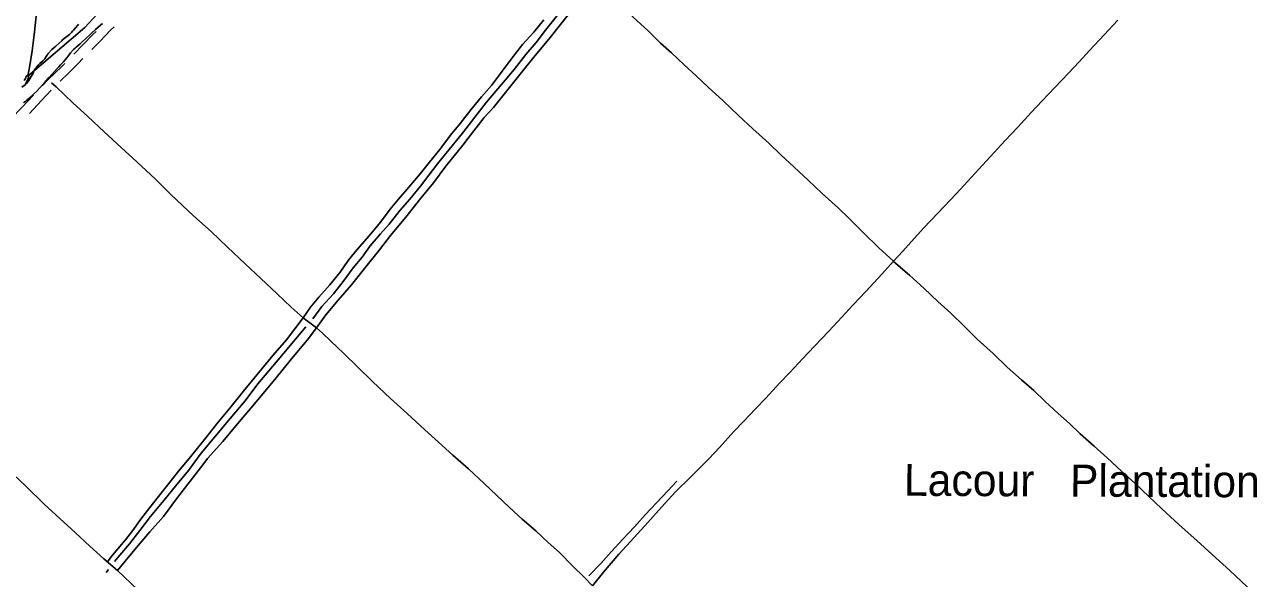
# Model space of a CAD drawing. Extents: x 3161514 to 3199414, y 831166 to 856601.
# Drawn here: x 3187801 to 3191633, y 845883 to 847621 of the extents above; entities that cross this region are included whole.
import ezdxf

# ---------------------------------------------------------------- set-up
doc = ezdxf.new("R2010")
doc.units = 0
for name, color, linetype in [('V-ROAD-CNTR', 7, 'Continuous'), ('V-SITE-VEGE', 7, 'Continuous'), ('V-TOPO-GNAM-IDEN', 7, 'Continuous'), ('V-TOPO-SHOR', 7, 'Continuous')]:
    doc.layers.add(name, color=color, linetype=linetype)

msp = doc.modelspace()

# ---------------------------------------------------------------- linework, layer by layer
at = {"layer": 'V-ROAD-CNTR'}
for points in [[(3188081.8, 847613.5), (3188070.1, 847602.1), (3188036.8, 847567.5), (3188011.6, 847542.3)], [(3188025.3, 847598.9), (3188015.3, 847588.5), (3187983.5, 847556.6), (3187955.3, 847527.4)], [(3187927.6, 847498.6), (3187918, 847488.8), (3187874.8, 847448), (3187856.4, 847428.4)], [(3187983.7, 847513.6), (3187969.1, 847498.4), (3187939.1, 847467.4), (3187913.1, 847442.9)], [(3187884.7, 847414.7), (3187854.6, 847382.5), (3187816.4, 847341.6)], [(3187829.1, 847399.2), (3187792.7, 847360.1), (3187760.6, 847326.3)]]:
    msp.add_lwpolyline(points, dxfattribs=at)
at = {"layer": 'V-SITE-VEGE'}
for points in [[(3189271, 847360.2), (3189316.5, 847417.6), (3189362.7, 847475.3), (3189401.3, 847523.1), (3189444.1, 847574.2), (3189484.6, 847625.1), (3189527.3, 847679.8), (3189562.1, 847724.7), (3189586, 847756.9), (3189613.5, 847793.1)], [(3189990.5, 847380.6), (3189943.4, 847423.8), (3189905.2, 847459), (3189867.8, 847493.4), (3189828, 847531.9), (3189794.3, 847562.1), (3189754.1, 847601.2), (3189709.5, 847642.6), (3189666.8, 847683.8), (3189631.8, 847718.3), (3189586, 847756.9)], [(3187792.8, 847424.2), (3187803.3, 847431.2), (3187807.4, 847435), (3187811.8, 847440.4), (3187813.7, 847443.2), (3187814.4, 847444.6), (3187825.2, 847462.8), (3187828.7, 847469.6), (3187830.3, 847474), (3187833.3, 847479.6), (3187835.2, 847482), (3187837, 847485), (3187839.3, 847488.1), (3187843.7, 847493), (3187848.8, 847498.4), (3187857.2, 847505.9), (3187859.9, 847508.5), (3187862.3, 847510.8), (3187864.1, 847513.2), (3187868.5, 847520.2), (3187874.7, 847529.3), (3187886.6, 847541.5), (3187893.1, 847546.7), (3187897.5, 847550.9), (3187900, 847553), (3187918.3, 847569.6), (3187920.4, 847571.8), (3187929.5, 847579.7), (3187933.2, 847582.5), (3187941.8, 847589.4), (3187946.4, 847593.6), (3187948.7, 847596.4), (3187951.5, 847599.4), (3187954.5, 847602.9), (3187961, 847610), (3187968, 847618.4), (3187970, 847621.2)], [(3188045.8, 847623.3), (3188031.6, 847612), (3188023.3, 847605), (3188011, 847592.8), (3188004.7, 847586.4), (3187995.2, 847578.2), (3187979.7, 847563.9), (3187975, 847559.5), (3187963, 847548.9), (3187959.3, 847545.9), (3187954.2, 847541.9), (3187945.4, 847532), (3187943.1, 847528.8), (3187933.1, 847515.4), (3187922.9, 847503.7), (3187915.5, 847496), (3187913.4, 847493.6), (3187908.1, 847487.3), (3187902.8, 847481.9), (3187895.1, 847472.8), (3187877.7, 847454.3), (3187873.1, 847449.6), (3187872.2, 847448.4), (3187866.8, 847442.5), (3187865.2, 847440.4), (3187857.1, 847431.3), (3187839.3, 847411.6), (3187828.6, 847401.8), (3187814.7, 847388.2), (3187808.4, 847383), (3187803.6, 847378.5), (3187801, 847377.4), (3187797.5, 847374.8)], [(3188881, 846957.7), (3188916.5, 847000.9), (3188946.4, 847041.6), (3188972.8, 847072.6), (3189005.7, 847110.4), (3189040.6, 847152), (3189070.5, 847189), (3189102.8, 847228.7), (3189136.1, 847273.5), (3189165.6, 847309.8), (3189199.1, 847352.5), (3189232.8, 847393.5), (3189264.2, 847429.4), (3189292.1, 847466.7), (3189326.3, 847511.2), (3189361.7, 847558), (3189396.7, 847596.3), (3189428.7, 847635.5)], [(3191226.9, 847633.5), (3191183.8, 847587.7), (3191138.5, 847539), (3191105.8, 847503.4), (3191072.2, 847467.8), (3191029.1, 847423.1), (3190989.7, 847380.6), (3190955.7, 847344), (3190914.1, 847298.7), (3190874.1, 847256.4), (3190839, 847219.5), (3190802.6, 847179.5), (3190756.7, 847129.1), (3190720.1, 847089.8), (3190682.3, 847049.4), (3190619.1, 846983.2), (3190578.9, 846939.4), (3190552.8, 846909.5), (3190523.9, 846878.5), (3190487.8, 846837.2), (3190437.2, 846783.2), (3190396.6, 846740.1), (3190362, 846703.1), (3190321.4, 846659.2)], [(3188152.7, 847189.3), (3188104, 847234.4), (3188050.5, 847283.5), (3187999.8, 847331.7), (3187951.9, 847374.9), (3187899.6, 847424.7), (3187885.4, 847437.4)], [(3190256.5, 847132.3), (3190213, 847172.6), (3190171.4, 847212), (3190133.5, 847248.5), (3190083.6, 847293.2), (3190037.8, 847335.5), (3189990.5, 847380.6)], [(3188995.6, 847016.3), (3189043.2, 847075.8), (3189082.2, 847124.2), (3189121, 847175.9), (3189174.1, 847242.4), (3189191.5, 847264), (3189241.5, 847328.5), (3189271, 847360.2)], [(3188492.4, 846869.8), (3188436.5, 846922.5), (3188385.7, 846971.8), (3188330.5, 847020.9), (3188260.3, 847086.7), (3188211, 847135.3), (3188152.7, 847189.3)], [(3190523.9, 846878.5), (3190478.4, 846920.1), (3190429, 846968), (3190385.5, 847012), (3190350.4, 847045.3), (3190300.4, 847090.8), (3190256.5, 847132.3)], [(3188716.2, 846669.8), (3188745.1, 846710.2), (3188783.8, 846755.9), (3188825.8, 846803.7), (3188866.2, 846855.5), (3188913.7, 846914), (3188948.2, 846958.5), (3188995.6, 847016.3)], [(3188674.3, 846700.8), (3188697.6, 846734.2), (3188723, 846765.2), (3188757.4, 846804.1), (3188790, 846844.4), (3188815, 846880.1), (3188843.3, 846915), (3188881, 846957.7)], [(3188716.2, 846669.8), (3188674.3, 846700.8), (3188636.1, 846734.3), (3188592.7, 846776.5), (3188541.3, 846823.7), (3188492.4, 846869.8)], [(3190523.6, 846876.9), (3190573.7, 846834.2), (3190619.8, 846792.7), (3190663.3, 846751.6), (3190703.7, 846714.9), (3190746.2, 846673.5), (3190786.1, 846633.8), (3190835.9, 846589.3), (3190880.6, 846546.2), (3190925.1, 846506.5), (3190963.3, 846473), (3190998.6, 846439.8)], [(3188317.4, 846260.3), (3188365.3, 846319.5), (3188407.8, 846373.7), (3188444.5, 846417.5), (3188487.6, 846471), (3188530.2, 846523.5), (3188579.5, 846583.2), (3188621.8, 846631.8), (3188674, 846701), (3188674.3, 846700.8)], [(3188373.9, 846259.3), (3188422.1, 846313.1), (3188468.3, 846368.3), (3188510.5, 846417.8), (3188549.2, 846464), (3188589.2, 846512.4), (3188637.1, 846571.8), (3188686.2, 846630.9), (3188716.2, 846669.8)], [(3188947.8, 846447.9), (3188891.2, 846501), (3188844.2, 846547.5), (3188801.9, 846588.5), (3188760.6, 846627.8), (3188734.4, 846653), (3188716.2, 846669.8)], [(3190321.4, 846659.2), (3190276.8, 846611.7), (3190239.5, 846572.9), (3190199, 846529.2), (3190166.9, 846495.9), (3190123.9, 846449.2), (3190091.4, 846415.4), (3190055.2, 846376.3), (3190023.8, 846344.5), (3189978.3, 846294.7), (3189945.2, 846258.5), (3189887.4, 846200.9)], [(3189192.1, 846227.7), (3189143.4, 846270.5), (3189098, 846311), (3189055.2, 846349.7), (3189000, 846400.9), (3188947.8, 846447.9)], [(3190998.6, 846439.8), (3191039.9, 846401.1), (3191075.3, 846369.2), (3191109.4, 846337.6), (3191152.7, 846298.9), (3191193.6, 846261.4), (3191239.6, 846218.6), (3191281.4, 846181.8), (3191324.6, 846140.9)], [(3188092.1, 845909), (3188049.6, 845945.5), (3188005.8, 845985.4), (3187960.9, 846027.2), (3187911.5, 846072.2), (3187862.1, 846117.1), (3187805, 846173.3), (3187767.2, 846208.5), (3187732.4, 846241.2), (3187682.2, 846285.9)], [(3188317.4, 846260.3), (3188283.8, 846219.6), (3188253.1, 846181), (3188217.1, 846135.1), (3188186.4, 846096.9), (3188162.3, 846065.4), (3188138.9, 846033.5), (3188117.5, 846004.9), (3188093.2, 845976.3), (3188071.5, 845950.2), (3188062, 845936.8)], [(3188116.4, 845937.9), (3188157.2, 845987.5), (3188193.6, 846029.6), (3188236.5, 846077.5), (3188277, 846133.6), (3188319.5, 846189), (3188359.5, 846240.1), (3188373.9, 846259.3)], [(3189360.3, 846069.7), (3189320.3, 846106.2), (3189280.2, 846144.5), (3189241.7, 846181.3), (3189192.1, 846227.7)], [(3189581.1, 845861.1), (3189614.9, 845903), (3189663.1, 845959.7), (3189711.6, 846012.1), (3189754.5, 846058.9), (3189797.5, 846107.3), (3189840.9, 846154.9), (3189887.4, 846200.9)], [(3191770.4, 845724.9), (3191731.1, 845765.8), (3191684.2, 845810.2), (3191631.8, 845857.9), (3191578.2, 845908.5), (3191522.9, 845959), (3191474.3, 846002.7), (3191419, 846052.3), (3191363.8, 846102.8), (3191324.6, 846140.9)], [(3189581.1, 845861.1), (3189554.6, 845888.1), (3189519.6, 845922.4), (3189477.6, 845964.7), (3189442.1, 845996), (3189403.6, 846033.3), (3189360.3, 846069.7)], [(3188328.5, 845681.7), (3188275.8, 845733.8), (3188239.7, 845768.1), (3188203, 845802.7), (3188156.3, 845848.2), (3188092.1, 845909), (3188116.4, 845937.9)]]:
    msp.add_lwpolyline(points, dxfattribs=at)
at = {"layer": 'V-TOPO-SHOR'}
msp.add_line((3188063.7, 845912), (3188057, 845901.9), dxfattribs=at)
for points in [[(3187811.7, 847458.9), (3187989.6, 847610.7), (3188530.7, 848197.7), (3188753.4, 848431.1), (3189043.4, 848685.7), (3189351, 849021.6)], [(3189172.9, 847280.2), (3189212, 847329.5), (3189248.4, 847376.5), (3189295.4, 847432.3), (3189335.8, 847479.7), (3189371.8, 847526.1), (3189403.8, 847563.7), (3189433.6, 847602.8), (3189466.9, 847644.3), (3189495.7, 847682.1), (3189524.7, 847717.9), (3189557.6, 847760.7)], [(3187811.7, 847458.9), (3187818, 847491.8), (3187824.7, 847537.8), (3187831.3, 847588), (3187838.7, 847656.1), (3187844.6, 847709.4), (3187848.1, 847755.6)], [(3187799.7, 847445), (3187801.6, 847447.5), (3187803.6, 847450.8), (3187805.5, 847455), (3187807.1, 847458.1), (3187808.5, 847460.4), (3187809.4, 847460.4), (3187812.2, 847459), (3187813.4, 847456.2), (3187812.9, 847453), (3187811.8, 847450.2), (3187810, 847445.9), (3187808.3, 847443.1), (3187807.2, 847439.4), (3187804.4, 847433.6), (3187802.8, 847431), (3187798.9, 847427.9)], [(3188943.1, 846994.9), (3188978.1, 847037.8), (3189008.7, 847072.6), (3189041.6, 847113.7), (3189067.8, 847148.3), (3189094.7, 847183.7), (3189122.7, 847217.4), (3189172.9, 847280.2)], [(3188704.7, 846697.3), (3188732.9, 846736), (3188768.8, 846776.2), (3188799.4, 846814.6), (3188830.8, 846857.4), (3188858.9, 846891.4), (3188884.2, 846926.2), (3188916.3, 846964.4), (3188943.1, 846994.9)], [(3188354.5, 846276), (3188397.4, 846327.8), (3188444.9, 846385.2), (3188492, 846440.7), (3188531.6, 846493.9), (3188578.2, 846548.7), (3188612.8, 846588.8), (3188682.4, 846672.9)], [(3188354.5, 846276), (3188314.4, 846222.4), (3188274.2, 846172.8), (3188237, 846128.3), (3188195.5, 846077.6), (3188162.4, 846034.2), (3188130, 845991.9), (3188100, 845956.6), (3188082.8, 845936.7)], [(3189569.8, 845892.2), (3189607.2, 845931.1), (3189639.2, 845967), (3189676.1, 846007.3), (3189712.6, 846045.2), (3189745.6, 846083.1), (3189782, 846121.6), (3189816.9, 846158.3), (3189844.7, 846188.5)]]:
    msp.add_lwpolyline(points, dxfattribs=at)

# ---------------------------------------------------------------- texts
at = {"layer": 'V-TOPO-GNAM-IDEN'}
msp.add_text('Lacour   Plantation', height=100, rotation=359.7335, dxfattribs=at).set_placement((3190556.6, 846143))

doc.saveas('drawing.dxf')
